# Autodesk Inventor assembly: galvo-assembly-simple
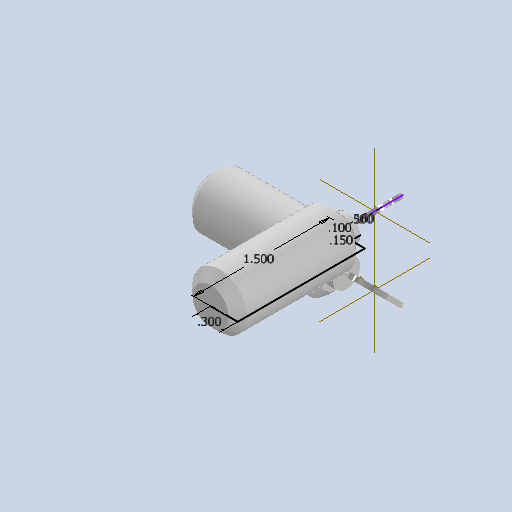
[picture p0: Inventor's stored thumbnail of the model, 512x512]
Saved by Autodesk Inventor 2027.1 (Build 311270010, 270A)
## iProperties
Created: 2026-08
Part Number: galvo-assembly-simple
Document SubType Name: Assembly
Designer: dunge
Author: dunge
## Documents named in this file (2)
- C:\Users\dunge\OneDrive\Documents\Inventor\Inventor\Inventor\simplified-drawings\galvo-assembly-simple.iam
- C:\Users\dunge\OneDrive\Documents\Inventor\Inventor\Inventor\simplified-drawings\simplified-galvo.ipt
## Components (2 placed, 1 different names)
1. simplified-galvo:1 — Mate:1, Angle:1, Mate:2
2. simplified-galvo:2 — Mate:1, Angle:1, Mate:2
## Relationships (3: Mate 2, Angle 1)
- Mate:1: simplified-galvo:1 ↔ simplified-galvo:2
- Angle:1: simplified-galvo:1 ↔ simplified-galvo:2
- Mate:2: simplified-galvo:1 ↔ simplified-galvo:2
